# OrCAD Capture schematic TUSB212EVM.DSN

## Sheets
1 PAGE2: size C; title: TUSB212EVM; rev: A; note: TUSB212 - INT063-001  TUSB214 -INT063-002
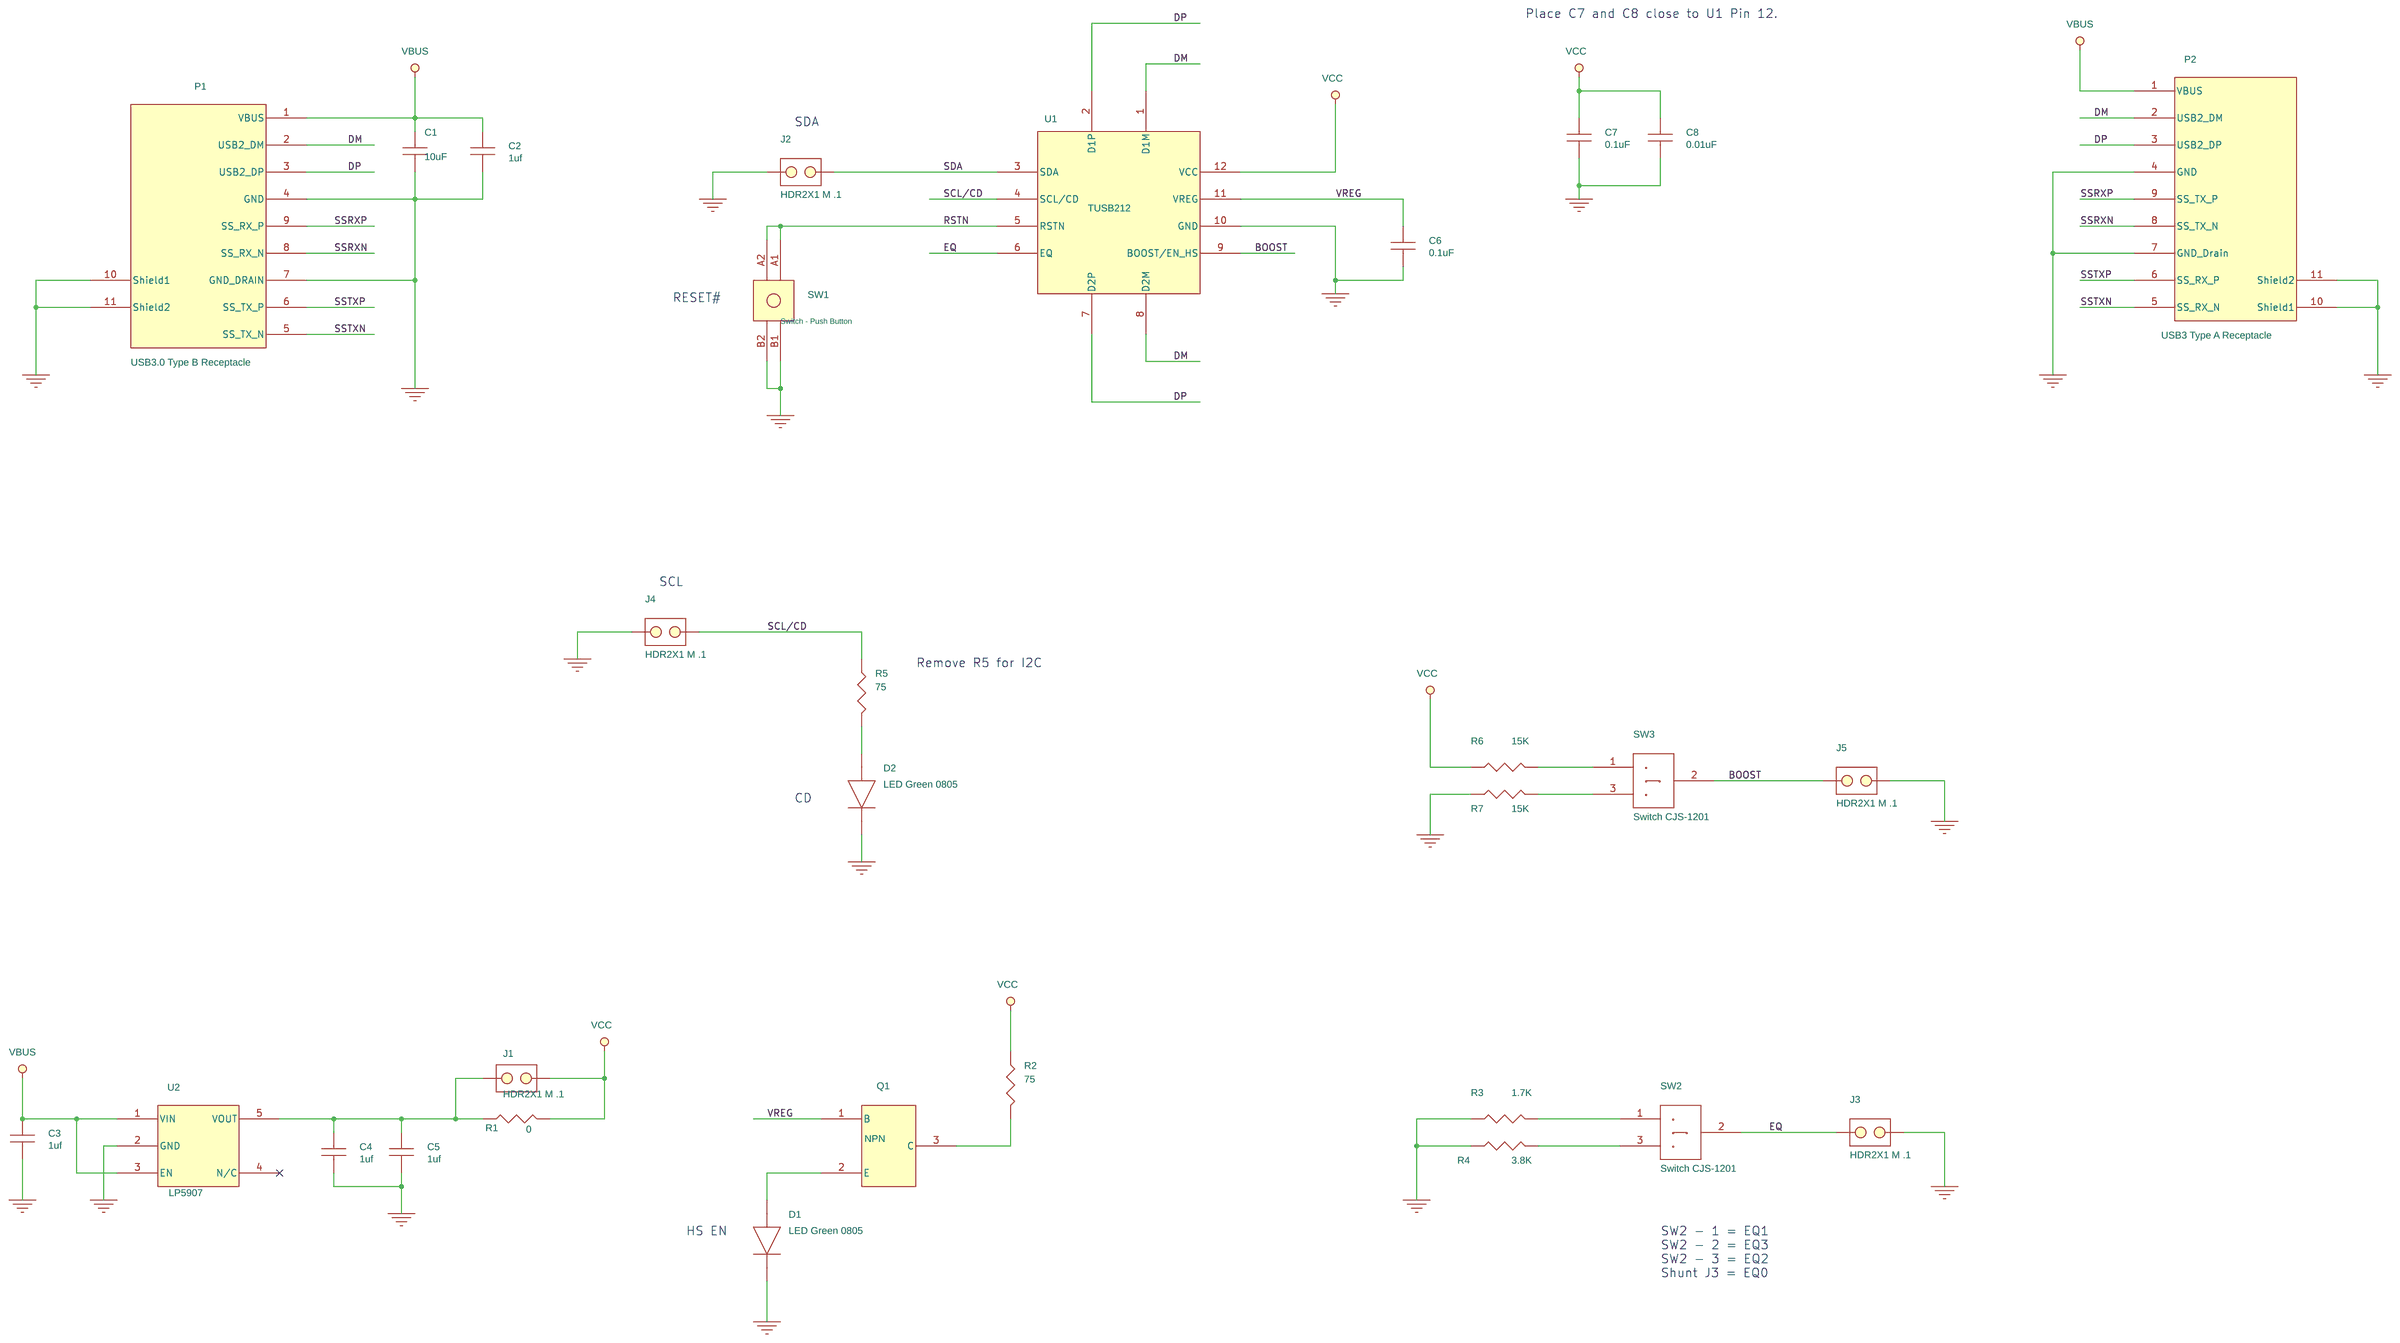
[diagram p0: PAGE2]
2 PAGE1

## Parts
C1  10uF  [cc0805]
C2  1uf  [cc0603]
C3  1uf  [cc0603]
C4  1uf  [cc0603]
C5  1uf  [cc0603]
C6  0.1uF  [cc0402]
C7  0.1uF  [cc0402]
C8  0.01uF  [cc0201]
D1  LED Green 0805
D2  LED Green 0805
J1  HDR2X1 M .1
J2  HDR2X1 M .1
J3  HDR2X1 M .1
J4  HDR2X1 M .1
J5  HDR2X1 M .1
P1  USB3.0 Type B Receptacle
P2  USB3 Type A Receptacle
Q1  NPN  [SOT-23]
R1  0  [r0805]
R2  75  [r0402]
R3  1.7K  [r0402]
R4  3.8K  [r0402]
R5  75  [r0402]
R6  15K  [r0402]
R7  15K  [r0402]
SW1  Switch - Push Button  [SW_THVT_EVQPAX05]
SW2  Switch CJS-1201  [cjs-1200b]
SW3  Switch CJS-1201  [cjs-1200b]
U1  TUSB212
U2  LP5907  [DBV_R-PDSO-G5]

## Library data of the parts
C1 = cc0805
C2-C5 = cc0603_1.0uf_25V
C6 C7 = cc0402
C8 = cc0201
D1 D2 = LED_Green_0805
J1-J5 = HDR2X1_M_.1
P1 = USB_3.0_Type_B_Receptacle
P2 = USB_3.0_Type_A_Receptacle
Q1 = MMBT2222L
R1 = r0805
R2-R7 = r0402
SW1 = Switch_-_Push_Button_0
SW2 SW3 = Switch_CJS-1201
U1 = TUSB212RWB_0
U2 = LP5907

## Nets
GND: C1.2 C2.2 C3.2 C4.2 C5.2 C6.2 C7.2 C8.2 D1.CATHODE D2.CATHODE J2.2 J3.1 J4.2 J5.2 P1.4(GND) P1.7(GND_DRAIN) P1.10(Shield1) P1.11(Shield2) P2.4(GND) P2.7(GND_Drain) P2.10(Shield1) P2.11(Shield2) R3.1 R4.1 R7.1 SW1.B1 SW1.B2 U1.10(GND) U2.2(GND)
VBUS: C1.1 C2.1 C3.1 P1.1(VBUS) P2.1(VBUS) U2.1(VIN) U2.3(EN)
VCC: C7.1 C8.1 J1.2 R1.2 R2.1 R6.1 U1.12(VCC)
BOOST: J5.1 SW3.2 U1.9(BOOST/EN_HS)
DM: P1.2(USB2_DM) P2.2(USB2_DM) U1.1(D1M) U1.8(D2M)
DP: P1.3(USB2_DP) P2.3(USB2_DP) U1.2(D1P) U1.7(D2P)
EQ: J3.2 SW2.2 U1.6(EQ)
RSTN: SW1.A1 SW1.A2 U1.5(RSTN)
SCL/CD: J4.1 R5.1 U1.4(SCL/CD)
SDA: J2.1 U1.3(SDA)
SSRXN: P1.8(SS_RX_N) P2.8(SS_TX_N)
SSRXP: P1.9(SS_RX_P) P2.9(SS_TX_P)
SSTXN: P1.5(SS_TX_N) P2.5(SS_RX_N)
SSTXP: P1.6(SS_TX_P) P2.6(SS_RX_P)
VREG: C6.1 Q1.1(B) U1.11(VREG)
N16640398: C4.1 C5.1 J1.1 R1.1 U2.5(VOUT)
N16640739: Q1.3(C) R2.2
N16641020: D1.ANNODE Q1.2(E)
N16642054: R3.2 SW2.1
N16642058: R4.2 SW2.3
N16642695: D2.ANNODE R5.2
N16643268: R6.2 SW3.1
N16643272: R7.2 SW3.3

Not connected (* = marked no-connect by the designer): U2 4(N/C)*

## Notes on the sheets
sheet 1
- Place C7 and C8 close to U1 Pin 12.
- SDA
- RESET#
- SCL
- Remove R5 for I2C
- CD
- HS EN
- SW2 - 1 = EQ1
  SW2 - 2 = EQ3
  SW2 - 3 = EQ2
  Shunt J3 = EQ0
